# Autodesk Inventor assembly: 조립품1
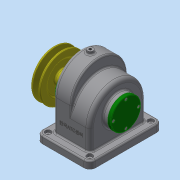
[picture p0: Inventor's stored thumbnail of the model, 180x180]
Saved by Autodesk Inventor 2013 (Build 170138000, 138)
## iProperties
Created: 2017-11
Part Number: 조립품1
Document SubType Name: Assembly
Designer: dgall
Author: dgall
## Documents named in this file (14)
- C:\Users\dgall\Desktop\조립품1.iam
- C:\Users\dgall\Desktop\본체.ipt
- C:\Users\dgall\Desktop\471107V1011\V-벨트풀리.ipt
- C:\Users\dgall\Desktop\471107V1011\뒤커버.ipt
- C:\Users\dgall\Desktop\471107V1011\멈춤나사 - M4 x 10.ipt
- 멈춤나사 - M4 x 10.ipt
- C:\Users\dgall\Desktop\471107V1011\베어링 6002.ipt
- C:\Users\dgall\Desktop\471107V1011\볼트 M3 x 8.ipt
- C:\Users\dgall\Desktop\471107V1011\스퍼기어.ipt
- C:\Users\dgall\Desktop\471107V1011\앞커버.ipt
- C:\Users\dgall\Desktop\471107V1011\오일 실 15 30 7.ipt
- C:\Users\dgall\Desktop\471107V1011\축.ipt
- C:\Users\dgall\Desktop\471107V1011\키 - 5 x 5 x 18.ipt
- C:\Users\dgall\Desktop\471107V1011\키 - 6 x 6 x 22.ipt
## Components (1 placed, 1 different names)
1. V-벨트풀리:1 — 플러쉬:1
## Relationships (1: Flush 1)
- 플러쉬:1 [Flush]: V-벨트풀리:1
